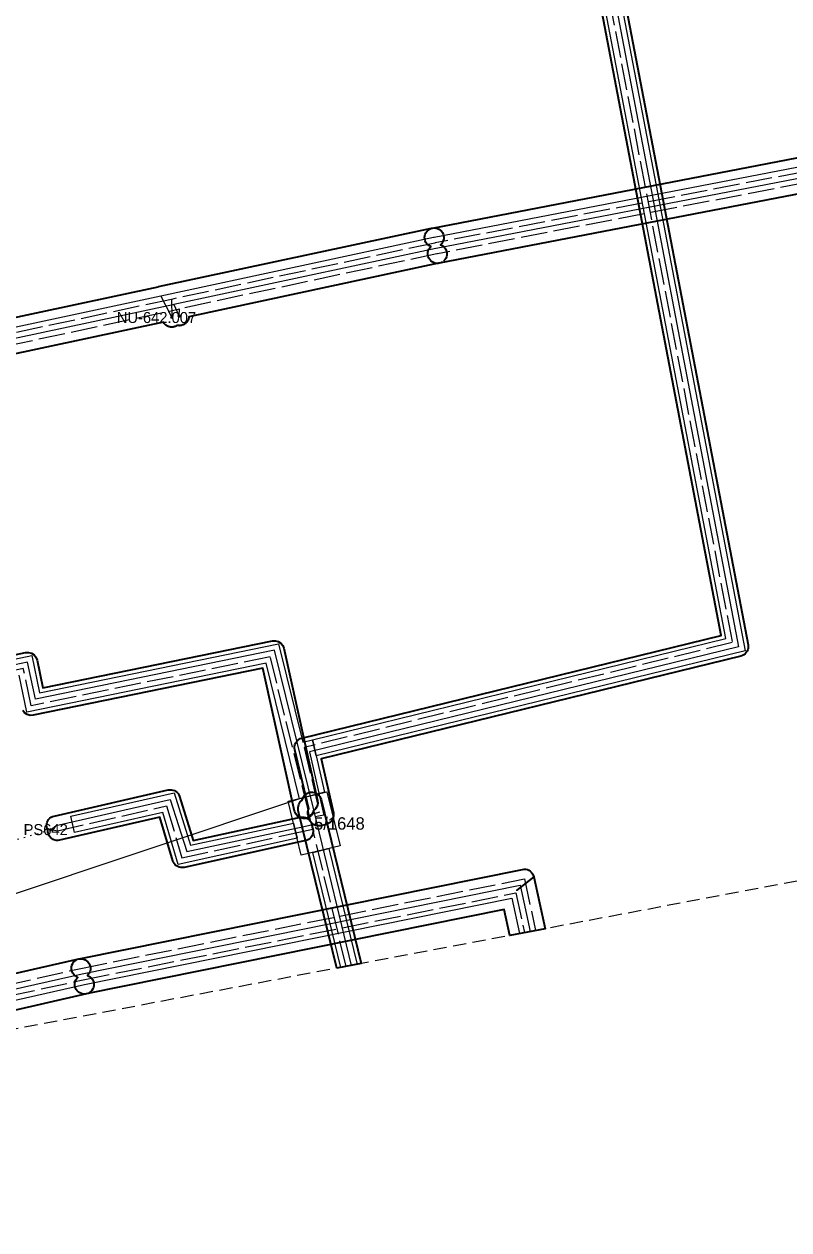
# Model space of a CAD drawing. Extents: x -452602 to -451136, y -1100088 to -1099653.
# Drawn here: x -452252 to -452196.4, y -1100042.4 to -1099954.9 of the extents above; entities that cross this region are included whole.
import ezdxf

# ---------------------------------------------------------------- set-up
doc = ezdxf.new("R2010")
doc.units = 0
doc.header["$LTSCALE"] = 0.32
doc.header["$PDMODE"] = 32
doc.header["$PDSIZE"] = 0.16
for name, pattern in [('DOTTED', [1.5, 0.3, -1.2]), ('LONG_DASHED', [7.5, 6, -1.5]), ('MEDIUM_DASHED', [4.5, 3, -1.5])]:
    doc.linetypes.add(name, pattern=pattern)
for name, color, linetype, lineweight in [('2', 7, 'Continuous', 13), ('3', 7, 'Continuous', 25), ('62', 7, 'MEDIUM_DASHED', 25), ('8', 7, 'Continuous', 35)]:
    doc.layers.add(name, color=color, linetype=linetype, lineweight=lineweight)
doc.layers.add('4', color=7, linetype='Continuous')
doc.layers.add('7', color=7, linetype='Continuous')

msp = doc.modelspace()

# ---------------------------------------------------------------- linework, layer by layer
at = {"layer": '2'}
for p, q in [((-452155.333, -1099957.462), (-452222.207, -1099970.354)), ((-452155.173, -1099958.246), (-452222.058, -1099971.14)), ((-452242.089, -1099974.607), (-452260.167, -1099978.477)), ((-452242.089, -1099974.607), (-452241.28, -1099976.165)), ((-452241.127, -1099975.217), (-452240.741, -1099976.058)), ((-452230.842, -1100012.441), (-452230.97, -1100011.922)), ((-452231.776, -1100013.151), (-452230.724, -1100012.924)), ((-452230.625, -1100012.393), (-452230.842, -1100012.441)), ((-452230.724, -1100012.924), (-452230.842, -1100012.441)), ((-452228.215, -1100023.224), (-452230.724, -1100012.924)), ((-452250.049, -1100013.363), (-452249.682, -1100013.057)), ((-452253.711, -1100025.179), (-452247.801, -1100023.829)), ((-452252.652, -1100025.755), (-452247.634, -1100024.612))]:
    msp.add_line(p, q, dxfattribs=at)
at = {"layer": '2', "linetype": 'LONG_DASHED'}
for p, q in [((-452155.248, -1099957.853), (-452222.134, -1099970.747)), ((-452155.097, -1099958.639), (-452221.983, -1099971.532)), ((-452241.297, -1099974.845), (-452260.491, -1099978.95)), ((-452241.297, -1099974.845), (-452241.28, -1099976.165)), ((-452240.741, -1099976.058), (-452240.728, -1099975.541)), ((-452231.287, -1100012.302), (-452231.354, -1100012.033)), ((-452230.695, -1100012.136), (-452231.287, -1100012.302)), ((-452231.038, -1100013.324), (-452231.287, -1100012.302)), ((-452250.049, -1100013.363), (-452249.594, -1100013.447)), ((-452231.703, -1100013.471), (-452231.038, -1100013.324)), ((-452228.609, -1100023.298), (-452231.038, -1100013.324)), ((-452253.41, -1100024.697), (-452247.89, -1100023.439)), ((-452253.122, -1100025.448), (-452247.711, -1100024.27))]:
    msp.add_line(p, q, dxfattribs=at)
for points in [[(-452210.396, -1099948.317), (-452200.553, -1099999.776), (-452231.662, -1100007.397), (-452230.555, -1100012.096), (-452230.695, -1100012.136)], [(-452222.134, -1099970.747), (-452222.178, -1099970.756), (-452241.297, -1099974.845)], [(-452221.983, -1099971.532), (-452222.027, -1099971.541), (-452240.728, -1099975.541)], [(-452260.776, -1099979.829), (-452260.323, -1099979.732), (-452241.13, -1099975.627), (-452240.728, -1099975.541)], [(-452231.354, -1100012.033), (-452234.13, -1100000.807), (-452251.502, -1100004.37), (-452252.071, -1100001.664), (-452256.379, -1100002.578), (-452255.809, -1100005.287), (-452267.758, -1100007.734), (-452280.049, -1100021.745), (-452282.164, -1100020.052), (-452285.193, -1100023.478), (-452283.32, -1100025.473), (-452291.913, -1100035.269), (-452320.083, -1100040.596), (-452321.74, -1100032.412), (-452361.32, -1100041.103), (-452368.581, -1100005.774), (-452374.217, -1100007.149), (-452374.659, -1100007.061)], [(-452249.594, -1100013.447), (-452241.659, -1100011.636), (-452240.541, -1100015.422), (-452231.703, -1100013.471)], [(-452247.89, -1100023.439), (-452215.66, -1100016.936), (-452214.842, -1100020.695)], [(-452247.711, -1100024.27), (-452216.28, -1100017.96), (-452215.649, -1100020.847)]]:
    msp.add_lwpolyline(points, dxfattribs=at)
at = {"layer": '2'}
for points in [[(-452210.005, -1099948.241), (-452200.09, -1100000.074), (-452231.262, -1100007.711), (-452230.221, -1100012.302), (-452230.625, -1100012.393)], [(-452222.207, -1099970.354), (-452222.259, -1099970.364), (-452242.089, -1099974.607)], [(-452222.058, -1099971.14), (-452222.103, -1099971.148), (-452241.127, -1099975.217)], [(-452241.127, -1099975.217), (-452241.213, -1099975.236), (-452260.407, -1099979.341), (-452260.591, -1099979.382)], [(-452230.97, -1100011.922), (-452233.825, -1100000.337), (-452251.193, -1100003.897), (-452251.762, -1100001.19), (-452256.853, -1100002.269), (-452256.282, -1100004.975), (-452267.969, -1100007.37), (-452280.097, -1100021.193), (-452282.212, -1100019.502), (-452285.734, -1100023.486), (-452283.859, -1100025.484), (-452292.551, -1100035.39), (-452319.689, -1100040.522), (-452321.428, -1100031.934), (-452361.009, -1100040.625), (-452368.273, -1100005.285), (-452374.31, -1100006.761), (-452374.659, -1100007.061)], [(-452249.682, -1100013.057), (-452241.387, -1100011.164), (-452240.197, -1100014.962), (-452231.776, -1100013.151)], [(-452247.801, -1100023.829), (-452215.967, -1100017.405), (-452215.236, -1100020.769)], [(-452247.634, -1100024.612), (-452216.582, -1100018.346), (-452216.022, -1100020.918)]]:
    msp.add_lwpolyline(points, dxfattribs=at)
at = {"layer": '2', "linetype": 'DOTTED'}
msp.add_lwpolyline([(-452256.061, -1100014.059), (-452253.424, -1100014.326), (-452250.049, -1100013.363)], dxfattribs=at)
at = {"layer": '3'}
for points in [[(-452231.044, -1100006.833), (-452201.018, -1099999.478), (-452206.361, -1099971.542), (-452209.976, -1099952.669), (-452208.8, -1099952.407), (-452205.439, -1099969.98), (-452199.625, -1100000.373), (-452230.785, -1100008.006)], [(-452232.173, -1100013.98), (-452240.819, -1100015.893), (-452241.937, -1100012.109), (-452248.354, -1100013.567), (-452248.613, -1100012.396), (-452241.116, -1100010.691), (-452239.925, -1100014.494), (-452232.439, -1100012.89)], [(-452228.999, -1100023.372), (-452231.029, -1100015.021), (-452229.87, -1100014.739), (-452227.822, -1100023.149)]]:
    msp.add_lwpolyline(points, close=True, dxfattribs=at)
for points in [[(-452257.326, -1100001.961), (-452251.453, -1100000.715), (-452250.883, -1100003.426), (-452233.528, -1099999.867), (-452231.762, -1100007.009), (-452231.044, -1100006.833), (-452230.193, -1100010.651), (-452231.993, -1100011.115), (-452320.476, -1100040.671)], [(-452231.993, -1100011.115), (-452234.427, -1100001.276), (-452251.812, -1100004.841), (-452252.38, -1100002.138)]]:
    msp.add_lwpolyline(points, dxfattribs=at)
at = {"layer": '3', "lineweight": 13}
msp.add_lwpolyline([(-452232.829, -1100011.295), (-452230.012, -1100010.607), (-452229.052, -1100014.538), (-452231.868, -1100015.226)], close=True, dxfattribs=at)
at = {"layer": '4'}
for p in [(-452241.28, -1099976.165), (-452240.741, -1099976.058), (-452250.049, -1100013.363)]:
    msp.add_point(p, dxfattribs=at)
at = {"layer": '62'}
msp.add_lwpolyline([(-451137.485, -1099816.961), (-452572.169, -1100088.267), (-452602.314, -1099919.678), (-451137.485, -1099652.838), (-451136.368, -1099701.963)], close=True, dxfattribs=at)
at = {"layer": '7'}
msp.add_point((-452250.049, -1100013.363), dxfattribs=at)
at = {"layer": '8'}
for points in [[(-452209.317, -1099948.109), (-452199.402, -1099999.943), (-452199.39, -1100000.06), (-452199.397, -1100000.178), (-452199.424, -1100000.293), (-452199.471, -1100000.402), (-452199.534, -1100000.501), (-452199.614, -1100000.588), (-452199.707, -1100000.661), (-452199.811, -1100000.717), (-452199.923, -1100000.754), (-452230.427, -1100008.227), (-452229.539, -1100012.148), (-452229.523, -1100012.257), (-452229.524, -1100012.367), (-452229.543, -1100012.475), (-452229.579, -1100012.579), (-452229.63, -1100012.677), (-452229.696, -1100012.765), (-452229.775, -1100012.842), (-452229.865, -1100012.905), (-452229.964, -1100012.953), (-452230.069, -1100012.986), (-452230.473, -1100013.076), (-452230.496, -1100013.081), (-452230.57, -1100013.09), (-452230.68, -1100013.091), (-452230.789, -1100013.073), (-452230.894, -1100013.039), (-452230.992, -1100012.989), (-452231.081, -1100012.924), (-452231.159, -1100012.846), (-452231.223, -1100012.757), (-452231.273, -1100012.658), (-452231.307, -1100012.553), (-452231.323, -1100012.444), (-452231.362, -1100012.349), (-452231.386, -1100012.249), (-452231.395, -1100012.147), (-452231.389, -1100012.045), (-452231.368, -1100011.944), (-452231.332, -1100011.848), (-452232.344, -1100007.557), (-452232.361, -1100007.437), (-452232.358, -1100007.316), (-452232.333, -1100007.197), (-452232.289, -1100007.084), (-452232.225, -1100006.981), (-452232.145, -1100006.89), (-452232.05, -1100006.814), (-452231.944, -1100006.756), (-452231.829, -1100006.717), (-452201.366, -1099999.255), (-452211.084, -1099948.448)], [(-452154.965, -1099959.326), (-452221.851, -1099972.22), (-452221.927, -1099972.23), (-452222.043, -1099972.23), (-452222.157, -1099972.21), (-452222.267, -1099972.172), (-452222.369, -1099972.116), (-452222.46, -1099972.044), (-452222.538, -1099971.958), (-452222.601, -1099971.861), (-452222.646, -1099971.754), (-452222.674, -1099971.641), (-452222.682, -1099971.525), (-452222.671, -1099971.41), (-452222.642, -1099971.297), (-452222.594, -1099971.191), (-452222.529, -1099971.095), (-452222.449, -1099971.011), (-452222.559, -1099970.959), (-452222.658, -1099970.89), (-452222.743, -1099970.804), (-452222.813, -1099970.705), (-452222.864, -1099970.595), (-452222.896, -1099970.478), (-452222.907, -1099970.358), (-452222.898, -1099970.237), (-452222.867, -1099970.12), (-452222.817, -1099970.01), (-452222.748, -1099969.91), (-452222.664, -1099969.823), (-452222.565, -1099969.752), (-452222.457, -1099969.699), (-452222.34, -1099969.666), (-452155.466, -1099956.775)], [(-452260.305, -1099977.79), (-452242.27, -1099973.931), (-452242.259, -1099973.929), (-452242.235, -1099973.923), (-452222.405, -1099969.679), (-452222.391, -1099969.676), (-452222.34, -1099969.666), (-452222.219, -1099969.655), (-452222.098, -1099969.664), (-452221.981, -1099969.694), (-452221.871, -1099969.744), (-452221.771, -1099969.812), (-452221.684, -1099969.896), (-452221.613, -1099969.994), (-452221.56, -1099970.103), (-452221.526, -1099970.219), (-452221.513, -1099970.339), (-452221.521, -1099970.46), (-452221.549, -1099970.578), (-452221.598, -1099970.689), (-452221.664, -1099970.789), (-452221.747, -1099970.877), (-452221.638, -1099970.929), (-452221.54, -1099970.998), (-452221.455, -1099971.083), (-452221.385, -1099971.182), (-452221.334, -1099971.291), (-452221.302, -1099971.407), (-452221.29, -1099971.527), (-452221.299, -1099971.647), (-452221.329, -1099971.764), (-452221.378, -1099971.874), (-452221.446, -1099971.974), (-452221.529, -1099972.061)], [(-452221.626, -1099972.132), (-452221.734, -1099972.186), (-452221.85, -1099972.22), (-452221.888, -1099972.227), (-452240.043, -1099976.111), (-452240.047, -1099976.149), (-452240.054, -1099976.194), (-452240.065, -1099976.239), (-452240.078, -1099976.283), (-452240.094, -1099976.326), (-452240.113, -1099976.367), (-452240.135, -1099976.408), (-452240.159, -1099976.447), (-452240.185, -1099976.484)], [(-452240.185, -1099976.484), (-452240.215, -1099976.519), (-452240.246, -1099976.553), (-452240.279, -1099976.584), (-452240.315, -1099976.613), (-452240.352, -1099976.64), (-452240.391, -1099976.664), (-452240.431, -1099976.685), (-452240.473, -1099976.704), (-452240.516, -1099976.721), (-452240.56, -1099976.734), (-452240.604, -1099976.744), (-452240.649, -1099976.752), (-452240.695, -1099976.756), (-452240.741, -1099976.758), (-452240.787, -1099976.756), (-452240.832, -1099976.752), (-452240.877, -1099976.744), (-452240.885, -1099976.742), (-452240.891, -1099976.747), (-452240.93, -1099976.771), (-452240.97, -1099976.793), (-452241.012, -1099976.811), (-452241.055, -1099976.828), (-452241.099, -1099976.841), (-452241.143, -1099976.851), (-452241.188, -1099976.859), (-452241.234, -1099976.863), (-452241.28, -1099976.865), (-452241.326, -1099976.863), (-452241.371, -1099976.859), (-452241.416, -1099976.851), (-452241.461, -1099976.841), (-452241.505, -1099976.828), (-452241.548, -1099976.811), (-452241.589, -1099976.793), (-452241.63, -1099976.771), (-452241.669, -1099976.747), (-452241.706, -1099976.72), (-452241.741, -1099976.691), (-452241.775, -1099976.66), (-452241.806, -1099976.626), (-452241.835, -1099976.591), (-452241.862, -1099976.554), (-452241.886, -1099976.515), (-452241.891, -1099976.506), (-452259.248, -1099980.218)], [(-452256.998, -1100001.585), (-452251.907, -1100000.505), (-452251.688, -1100000.493), (-452251.476, -1100000.55), (-452251.292, -1100000.67), (-452251.155, -1100000.841), (-452251.076, -1100001.046), (-452250.651, -1100003.072), (-452233.965, -1099999.651), (-452233.749, -1099999.641), (-452233.539, -1099999.697), (-452233.358, -1099999.815), (-452233.22, -1099999.983), (-452233.141, -1100000.185), (-452230.686, -1100011.239), (-452230.673, -1100011.457), (-452230.728, -1100011.669), (-452230.845, -1100011.854), (-452230.987, -1100011.971), (-452231.031, -1100012.144), (-452231.149, -1100012.329), (-452231.318, -1100012.469), (-452231.522, -1100012.549), (-452231.74, -1100012.562), (-452231.952, -1100012.508), (-452232.137, -1100012.39), (-452232.277, -1100012.221), (-452232.357, -1100012.017), (-452234.664, -1100001.631), (-452251.362, -1100005.055), (-452251.58, -1100005.065), (-452251.791, -1100005.008), (-452251.973, -1100004.888), (-452252.11, -1100004.718)], [(-452214.976, -1100016.787), (-452214.154, -1100020.565), (-452216.71, -1100021.048), (-452217.119, -1100019.168), (-452247.495, -1100025.298), (-452247.615, -1100025.311), (-452247.737, -1100025.304), (-452247.854, -1100025.276), (-452247.966, -1100025.228), (-452248.067, -1100025.161), (-452248.155, -1100025.078), (-452248.228, -1100024.981), (-452248.283, -1100024.873), (-452248.318, -1100024.757), (-452248.333, -1100024.637), (-452248.327, -1100024.516), (-452248.3, -1100024.398), (-452248.253, -1100024.286), (-452248.188, -1100024.184), (-452248.105, -1100024.095), (-452248.216, -1100024.044), (-452248.316, -1100023.976), (-452248.402, -1100023.891), (-452248.473, -1100023.792), (-452248.525, -1100023.683), (-452248.558, -1100023.567), (-452248.571, -1100023.446), (-452248.562, -1100023.325), (-452248.533, -1100023.207), (-452248.483, -1100023.097), (-452248.416, -1100022.996), (-452248.332, -1100022.909), (-452248.234, -1100022.837), (-452248.126, -1100022.783), (-452248.009, -1100022.749), (-452215.799, -1100016.249), (-452215.679, -1100016.236), (-452215.558, -1100016.243), (-452215.44, -1100016.271), (-452215.329, -1100016.319), (-452215.228, -1100016.385), (-452215.14, -1100016.467), (-452215.067, -1100016.564), (-452215.012, -1100016.671), (-452214.976, -1100016.787), (-452216.2, -1100017.759), (-452216.197, -1100017.76), (-452216.198, -1100017.758), (-452216.2, -1100017.759)], [(-452253.566, -1100024.014), (-452248.046, -1100022.757), (-452247.925, -1100022.741), (-452247.804, -1100022.746), (-452247.685, -1100022.772), (-452247.573, -1100022.818), (-452247.471, -1100022.883), (-452247.38, -1100022.964), (-452247.306, -1100023.06), (-452247.249, -1100023.167), (-452247.212, -1100023.282), (-452247.195, -1100023.403), (-452247.199, -1100023.524), (-452247.224, -1100023.643), (-452247.269, -1100023.755), (-452247.332, -1100023.859), (-452247.413, -1100023.949), (-452247.303, -1100023.998), (-452247.202, -1100024.064), (-452247.115, -1100024.147), (-452247.042, -1100024.243), (-452246.988, -1100024.351), (-452246.953, -1100024.466), (-452246.938, -1100024.586), (-452246.943, -1100024.706), (-452246.97, -1100024.824), (-452247.016, -1100024.935), (-452247.081, -1100025.037), (-452247.162, -1100025.126), (-452247.257, -1100025.2), (-452247.363, -1100025.257), (-452247.478, -1100025.294), (-452253.275, -1100026.615)]]:
    msp.add_lwpolyline(points, dxfattribs=at)
for points in [[(-452240.719, -1100010.954), (-452239.72, -1100014.143), (-452231.924, -1100012.466), (-452231.807, -1100012.45), (-452231.689, -1100012.454), (-452231.574, -1100012.477), (-452231.463, -1100012.519), (-452231.362, -1100012.579), (-452231.272, -1100012.655), (-452231.196, -1100012.745), (-452231.137, -1100012.847), (-452231.095, -1100012.957), (-452231.072, -1100013.073), (-452231.07, -1100013.191), (-452231.033, -1100013.296), (-452231.013, -1100013.406), (-452231.012, -1100013.518), (-452231.028, -1100013.629), (-452231.061, -1100013.735), (-452231.111, -1100013.835), (-452231.177, -1100013.926), (-452231.255, -1100014.005), (-452231.346, -1100014.071), (-452231.446, -1100014.121), (-452231.552, -1100014.155), (-452240.39, -1100016.106), (-452240.506, -1100016.122), (-452240.622, -1100016.118), (-452240.737, -1100016.094), (-452240.846, -1100016.053), (-452240.946, -1100015.993), (-452241.035, -1100015.918), (-452241.111, -1100015.829), (-452241.17, -1100015.729), (-452241.212, -1100015.621), (-452242.145, -1100012.464), (-452249.439, -1100014.129), (-452249.556, -1100014.146), (-452249.674, -1100014.142), (-452249.79, -1100014.119), (-452249.901, -1100014.076), (-452250.003, -1100014.015), (-452250.093, -1100013.938), (-452250.168, -1100013.847), (-452250.228, -1100013.745), (-452250.269, -1100013.634), (-452250.291, -1100013.517), (-452250.293, -1100013.399), (-452250.342, -1100013.292), (-452250.372, -1100013.177), (-452250.383, -1100013.06), (-452250.373, -1100012.942), (-452250.344, -1100012.828), (-452250.296, -1100012.72), (-452250.231, -1100012.621), (-452250.15, -1100012.535), (-452250.056, -1100012.464), (-452249.951, -1100012.41), (-452249.838, -1100012.374), (-452241.543, -1100010.481), (-452241.428, -1100010.465), (-452241.313, -1100010.467), (-452241.199, -1100010.489), (-452241.09, -1100010.53), (-452240.99, -1100010.587), (-452240.9, -1100010.661), (-452240.824, -1100010.748), (-452240.763, -1100010.847)], [(-452229.297, -1100023.428), (-452232.088, -1100011.973), (-452232.105, -1100011.755), (-452232.055, -1100011.542), (-452231.941, -1100011.355), (-452231.798, -1100011.231), (-452231.759, -1100011.068), (-452231.645, -1100010.881), (-452231.479, -1100010.738), (-452231.277, -1100010.653), (-452231.059, -1100010.636), (-452230.846, -1100010.686), (-452230.659, -1100010.8), (-452230.516, -1100010.966), (-452230.431, -1100011.168), (-452227.526, -1100023.093)]]:
    msp.add_lwpolyline(points, close=True, dxfattribs=at)

# ---------------------------------------------------------------- texts
at = {"layer": '3'}
msp.add_text('5/1648 ', height=0.9, dxfattribs=at).set_placement((-452230.94, -1100013.366))
at = {"layer": '4'}
for s, p in [('NU-642.007', (-452245.28, -1099976.565)), ('PS642 ', (-452252.049, -1100013.763))]:
    msp.add_text(s, height=0.8, dxfattribs=at).set_placement(p)

doc.saveas('drawing.dxf')
